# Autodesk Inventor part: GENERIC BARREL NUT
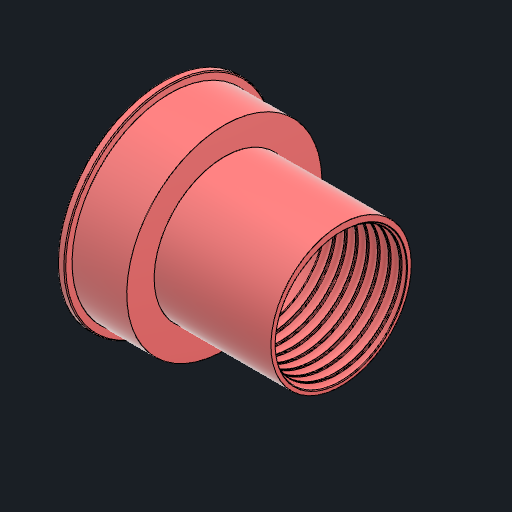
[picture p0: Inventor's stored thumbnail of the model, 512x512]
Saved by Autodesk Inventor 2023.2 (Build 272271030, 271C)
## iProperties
Created: 2023-04
Part Number: GENERIC BARREL NUT
Material: Generic
Document SubType Name: Modeling
Designer: AR
Mass: 30.3008 g
Surface Area: 171.95 cm^2
Volume: 30.3008 cm^3
Density: 1 g/cm^3
Appearance: Default
Author: AR
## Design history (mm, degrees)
derived "_2 SPOOL CORD WRAP MP.ipt"
feature "GENERIC BARREL NUT::_2 SPOOL CORD WRAP MP.ipt" dims "d0" = 10
tag "TaggingFeature1"
node "GENERIC BARREL NUT"
